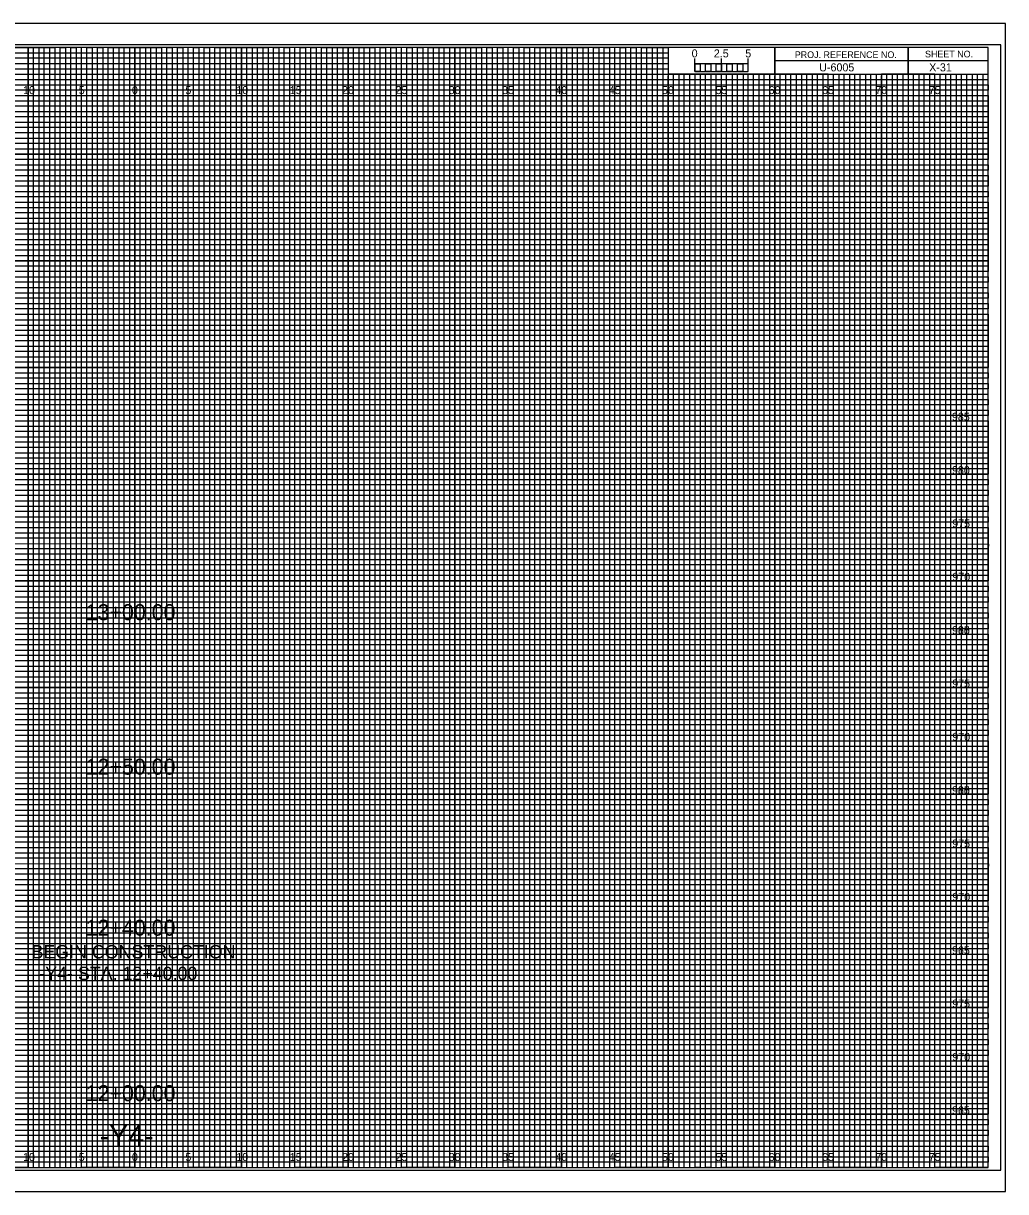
# Model space of a CAD drawing. Extents: x -7 to 162, y -2 to 107.
# Drawn here: x 69.5 to 161.7, y -2.3 to 107.3 of the extents above; entities that cross this region are included whole.
import ezdxf

# ---------------------------------------------------------------- set-up
doc = ezdxf.new("R2010")
doc.units = 0
for name, color, linetype in [('Prop XS Alignment Label', 7, 'Continuous'), ('Prop XS Bar Scale Labels', 7, 'Continuous'), ('Prop XS Elevation Labels', 7, 'Continuous'), ('Prop XS Label Text', 7, 'Continuous'), ('Prop XS Offset Labels', 7, 'Continuous'), ('Prop XS Project Number', 7, 'Continuous'), ('Prop XS Sheet Number', 7, 'Continuous'), ('Prop XS Station Labels', 7, 'Continuous'), ('Sheet Cross Section CELL', 7, 'Continuous'), ('Sheet Cross Section Grid Major CELL', 7, 'Continuous'), ('Sheet Cross Section Grid Middle CELL', 7, 'Continuous'), ('Sheet Cross Section Grid Minor 1 CELL', 7, 'Continuous'), ('Sheet Cross Section Grid Minor 2 CELL', 7, 'Continuous'), ('Sheet Cross Section Scale CELL', 7, 'Continuous'), ('Sheet Cutting Line CELL', 7, 'Continuous'), ('Sheet DOT Grid CELL', 7, 'Continuous'), ('Sheet Plot Border Inside CELL', 7, 'Continuous'), ('Sheet Plot Border Outside CELL', 7, 'Continuous')]:
    doc.layers.add(name, color=color, linetype=linetype)

msp = doc.modelspace()

# ---------------------------------------------------------------- linework, layer by layer
at = {"layer": 'Sheet Cross Section CELL'}
for p, q in [((152.5, 105), (152.5, 102.5)), ((152.5, 102.5), (152.5, 105)), ((160, 103.75), (140, 103.75)), ((140, 103.75), (140, 102.5)), ((140, 102.5), (160, 102.5))]:
    msp.add_line(p, q, dxfattribs=at)
for points in [[(160, 105), (0, 105), (0, 0), (160, 0)], [(140, 105), (130, 105), (130, 102.52), (140, 102.52)], [(160, 105), (140, 105), (140, 102.5), (160, 102.5)]]:
    msp.add_lwpolyline(points, close=True, dxfattribs=at)
at = {"layer": 'Sheet Cross Section Grid Major CELL'}
for p, q in [((75, 105), (70, 105)), ((70, 105), (70, 0)), ((75, 0), (75, 105)), ((85, 105), (80, 105)), ((80, 105), (80, 0)), ((85, 0), (85, 105)), ((95, 105), (90, 105)), ((90, 105), (90, 0)), ((95, 0), (95, 105)), ((105, 105), (100, 105)), ((100, 105), (100, 0)), ((105, 0), (105, 105)), ((115, 105), (110, 105)), ((110, 105), (110, 0)), ((115, 0), (115, 105)), ((125, 105), (120, 105)), ((120, 105), (120, 0)), ((125, 0), (125, 105)), ((130, 105), (130, 0)), ((135, 0), (135, 102.5)), ((145, 102.5), (140, 102.5)), ((140, 102.5), (140, 0)), ((145, 0), (145, 102.5)), ((155, 102.5), (150, 102.5)), ((150, 102.5), (150, 0)), ((155, 0), (155, 102.5)), ((70, 0), (65, 0)), ((80, 0), (75, 0)), ((90, 0), (85, 0)), ((100, 0), (95, 0)), ((110, 0), (105, 0)), ((120, 0), (115, 0)), ((130, 0), (125, 0)), ((140, 0), (135, 0)), ((150, 0), (145, 0)), ((160, 0), (155, 0)), ((160, 0), (160, 0))]:
    msp.add_line(p, q, dxfattribs=at)
for points in [[(0, 100), (160, 100), (160, 95), (0, 95)], [(0, 90), (160, 90), (160, 85), (0, 85)], [(0, 80), (160, 80), (160, 75), (0, 75)], [(0, 70), (160, 70), (160, 65), (0, 65)], [(0, 60), (160, 60), (160, 55), (0, 55)], [(0, 50), (160, 50), (160, 45), (0, 45)], [(0, 40), (160, 40), (160, 35), (0, 35)], [(0, 30), (160, 30), (160, 25), (0, 25)], [(0, 20), (160, 20), (160, 15), (0, 15)], [(0, 10), (160, 10), (160, 5), (0, 5)]]:
    msp.add_lwpolyline(points, dxfattribs=at)
at = {"layer": 'Sheet Cross Section Grid Middle CELL'}
for points in [[(67.5, 105), (72.5, 105), (72.5, 0), (77.5, 0), (77.5, 105), (82.5, 105), (82.5, 0), (87.5, 0), (87.5, 105), (92.5, 105), (92.5, 0), (97.5, 0), (97.5, 105), (102.5, 105), (102.5, 0), (107.5, 0), (107.5, 105), (112.5, 105), (112.5, 0), (117.5, 0), (117.5, 105), (122.5, 105), (122.5, 0), (127.5, 0), (127.5, 105), (129.97, 105), (130, 105), (130, 102.5), (132.5, 102.5), (132.5, 0), (137.5, 0), (137.5, 102.5), (142.5, 102.5), (142.5, 0), (147.5, 0), (147.5, 102.5), (152.5, 102.5), (152.5, 0), (157.5, 0), (157.5, 102.5)], [(0, 102.5), (137.5, 102.5)], [(0, 92.5), (160, 92.5), (160, 97.5), (0, 97.5)], [(0, 82.5), (160, 82.5), (160, 87.5), (0, 87.5)], [(0, 72.5), (160, 72.5), (160, 77.5), (0, 77.5)], [(0, 62.5), (160, 62.5), (160, 67.5), (0, 67.5)], [(0, 52.5), (160, 52.5), (160, 57.5), (0, 57.5)], [(0, 42.5), (160, 42.5), (160, 47.5), (0, 47.5)], [(0, 32.5), (160, 32.5), (160, 37.5), (0, 37.5)], [(0, 22.5), (160, 22.5), (160, 27.5), (0, 27.5)], [(0, 12.5), (160, 12.5), (160, 17.5), (0, 17.5)], [(0, 2.5), (160, 2.5), (160, 7.5), (0, 7.5)]]:
    msp.add_lwpolyline(points, dxfattribs=at)
at = {"layer": 'Sheet Cross Section Grid Minor 1 CELL'}
for p, q in [((0, 104.5), (130, 104.5)), ((130, 104.5), (130, 103.99)), ((130, 103.99), (0, 103.99)), ((0, 103.5), (130, 103.5)), ((130, 102.95), (0, 102.95)), ((130, 103.5), (130, 102.95)), ((0, 102), (160, 102))]:
    msp.add_line(p, q, dxfattribs=at)
for points in [[(0, 101.5), (135, 101.5), (160, 101.5), (160, 101), (0, 101)], [(0, 100.5), (160, 100.5), (160, 99.5), (0, 99.5)], [(0, 99), (160, 99), (160, 98.5), (0, 98.49)], [(0, 98), (160, 98), (160, 97), (0, 97)], [(0, 96.5), (160, 96.5), (160, 96), (0, 96)], [(0, 95.5), (160, 95.5), (160, 94.5), (0, 94.5)], [(0, 94), (160, 94), (160, 93.5), (0, 93.5)], [(0, 93), (160, 93), (160, 92), (0, 92)], [(0, 91.5), (160, 91.5), (160, 91), (0, 91)], [(0, 90.5), (160, 90.5), (160, 89.5), (0, 89.5)], [(0, 89), (160, 89), (160, 88.5), (0, 88.5)], [(0, 88), (160, 88), (160, 86.98), (160, 86.5), (160, 86), (0, 86)], [(0, 87), (160, 87), (160, 86.5), (0, 86.5)], [(0, 85.5), (160, 85.5), (160, 84.5), (0, 84.52)], [(0, 84.52), (160, 84.5), (160, 84), (0, 84)], [(0, 83.5), (160, 83.5), (160, 83), (0, 83)], [(0, 82), (160, 82), (160, 81.5), (0, 81.5)], [(0, 81), (160, 81), (160, 80.5), (0, 80.5)], [(-0.04, 79.45), (160, 79.45), (160, 78.94), (-0.04, 78.94)], [(0, 78.5), (160, 78.5), (160, 78), (0, 78)], [(0, 77), (160, 77), (160, 76.5), (0, 76.5)], [(0, 76), (160, 76), (160, 75.5), (0, 75.5)], [(0, 74.5), (160, 74.5), (160, 74), (0, 74)], [(0, 73.5), (160, 73.5), (160, 73), (0, 73)], [(0, 72), (160, 72), (160, 71.5), (0, 71.5)], [(0, 71), (160, 71), (160, 70.5), (0, 70.5)], [(0, 69.5), (160, 69.5), (160, 68.99), (0, 69)], [(0, 68.5), (160, 68.5), (160, 68), (0, 68)], [(0, 67), (160, 67), (160, 66.5), (0, 66.5)], [(0, 66), (160, 66), (160, 65.5), (0, 65.5)], [(0, 64.5), (160, 64.5), (160, 64), (0, 64)], [(0, 63.5), (160, 63.5), (160, 63), (0, 63)], [(0, 62), (160, 62), (160, 61.5), (0, 61.5)], [(0, 61), (160, 61), (160, 60.5), (0, 60.5)], [(0, 59.5), (160, 59.5), (160, 59), (0, 59)], [(0, 58.5), (160.03, 58.45), (160, 58), (0, 58)], [(0, 57), (160, 57), (160, 56.5), (0, 56.5)], [(0, 56), (160, 56), (160, 55.5), (0, 55.5)], [(0, 54.5), (160, 54.5), (160, 54), (0, 54)], [(0, 53.5), (160, 53.5), (160, 53), (0, 53)], [(0, 52), (160, 52), (160, 51.5), (0, 51.5)], [(0, 51), (160, 51), (160, 50.5), (0, 50.5)], [(0, 49.5), (160, 49.5), (160, 49), (0, 49)], [(0, 48.5), (160, 48.5), (160, 48), (0, 48)], [(0, 47), (160, 47), (160, 46.5), (0, 46.5)], [(0, 46), (160, 46), (160, 45.5), (0, 45.5)], [(0, 44.5), (160, 44.5), (160, 44), (0, 44)], [(0, 43.5), (160, 43.5), (160, 43), (0, 43)], [(0, 42), (160, 42), (160, 41.5), (0, 41.5)], [(0, 41), (160, 41), (160, 40.5), (0, 40.5)], [(0, 39.5), (160, 39.5), (160, 38.99), (0, 39)], [(0, 38.5), (160, 38.5), (160, 38), (0, 38)], [(0, 37), (160, 37), (160, 36.5), (0, 36.5)], [(0, 36), (160, 36), (160, 35.5), (0, 35.5)], [(0, 34.5), (160, 34.5), (160, 34), (0, 34)], [(0, 33.5), (160, 33.5), (160, 33), (0, 33)], [(0, 32), (160, 32), (160, 31.5), (0, 31.5)], [(0, 31), (160, 31), (160, 30.5), (0, 30.5)], [(0, 29.5), (160, 29.5), (160, 29), (0, 29)], [(0, 28.5), (160.03, 28.46), (160, 28), (0, 28)], [(0, 27), (160, 27), (160, 26.5), (0, 26.5)], [(0, 26), (160, 26), (160, 25.5), (0, 25.5)], [(0, 24.5), (160, 24.5), (160, 24), (0, 24)], [(0, 23.5), (160, 23.5), (160, 23), (0, 23)], [(0, 22), (160, 22), (160, 21.5), (0, 21.5)], [(0, 21), (160, 21), (160, 20.5), (0, 20.5)], [(0, 19.5), (160, 19.5), (160, 19), (0, 19)], [(0, 18.5), (160, 18.5), (160, 18), (0, 18)], [(0, 17), (160, 17), (160, 16.5), (0, 16.5)], [(0, 16), (160, 16), (160, 15.5), (0, 15.5)], [(0, 14.5), (160, 14.5), (160, 14), (0, 14)], [(0, 13.5), (160, 13.5), (160, 13), (0, 13)], [(0, 12), (160, 12), (160, 11.5), (0, 11.5)], [(0, 11), (160, 11), (160, 10.5), (0, 10.5)], [(0, 9.5), (160, 9.5), (160, 9), (0, 9)], [(0, 8.5), (160, 8.5), (160, 8), (0, 8)], [(0, 7), (160, 7), (160, 6.5), (0, 6.5)], [(0, 6), (160, 6), (160, 5.5), (0, 5.5)], [(0, 4.5), (160, 4.5), (160, 4), (0, 4)], [(0, 3.5), (160, 3.5), (160, 3), (0, 3)], [(0, 2), (160, 2), (160, 1.5), (0, 1.5)], [(0, 1), (160, 1), (160, 0.5), (0, 0.5)]]:
    msp.add_lwpolyline(points, dxfattribs=at)
at = {"layer": 'Sheet Cross Section Grid Minor 2 CELL'}
for p, q in [((133.5, 102.5), (133, 102.5)), ((133, 102.5), (133, 0)), ((133.5, 0), (133.5, 102.5)), ((134.5, 102.5), (134, 102.5)), ((134, 102.5), (134, 0)), ((134.5, 0), (134.5, 102.5)), ((133, 0), (132.5, 0)), ((134, 0), (133.5, 0))]:
    msp.add_line(p, q, dxfattribs=at)
for points in [[(70, 0), (70.5, 0), (70.5, 105), (71, 105), (71, 0)], [(71, 0), (71.5, 0), (71.5, 105), (72, 105), (72, 0)], [(72.5, 0), (73, 0), (73, 105), (73.5, 105), (73.5, 0)], [(73.5, 0), (74, 0), (74, 105), (74.5, 105), (74.5, 0)], [(75, 0), (75.5, 0), (75.5, 105), (76, 105), (76, 0)], [(76, 0), (76.5, 0), (76.5, 105), (77, 105), (77, 0)], [(77.5, 0), (78, 0), (78, 105), (78.5, 105), (78.5, 0)], [(78.5, 0), (79, 0), (79, 105), (79.5, 105), (79.5, 0)], [(80, 0), (80.5, 0), (80.5, 105), (81, 105), (81, 0)], [(81, 0), (81.5, 0), (81.5, 105), (82, 105), (82, 0)], [(82.5, 0), (83, 0), (83, 105), (83.5, 105), (83.5, 0)], [(83.5, 0), (84, 0), (84, 105), (84.5, 105), (84.5, 0)], [(85, 0), (85.5, 0), (85.5, 105), (86, 105), (86, 0)], [(86, 0), (86.5, 0), (86.5, 105), (87, 105), (87, 0)], [(87.5, 0), (88, 0), (88, 105), (88.5, 105), (88.5, 0)], [(88.5, 0), (89, 0), (89, 105), (89.5, 105), (89.5, 0)], [(90, 0), (90.5, 0), (90.5, 105), (91, 105), (91, 0)], [(91, 0), (91.5, 0), (91.5, 105), (92, 105), (92, 0)], [(92.5, 0), (93, 0), (93, 105), (93.5, 105), (93.5, 0)], [(93.5, 0), (94, 0), (94, 105), (94.5, 105), (94.5, 0)], [(95, 0), (95.5, 0), (95.5, 105), (96, 105), (96, 0)], [(96, 0), (96.5, 0), (96.5, 105), (97, 105), (97, 0)], [(97.5, 0), (98, 0), (98, 105), (98.5, 105), (98.5, 0)], [(98.5, 0), (99, 0), (99, 105), (99.5, 105), (99.5, 0)], [(100, 0), (100.5, 0), (100.5, 105), (101, 105), (101, 0)], [(101, 0), (101.5, 0), (101.5, 105), (102, 105), (102, 0)], [(102.5, 0), (103, 0), (103, 105), (103.5, 105), (103.5, 0)], [(103.5, 0), (104, 0), (104, 105), (104.5, 105), (104.5, 0)], [(105, 0), (105.5, 0), (105.5, 105), (106, 105), (106, 0)], [(106, 0), (106.5, 0), (106.5, 105), (107, 105), (107, 0)], [(107.5, 0), (108, 0), (108, 105), (108.5, 105), (108.5, 0)], [(108.5, 0), (109, 0), (109, 105), (109.5, 105), (109.5, 0)], [(110, 0), (110.5, 0), (110.5, 105), (111, 105), (111, 0)], [(111, 0), (111.5, 0), (111.5, 105), (112, 105), (112, 0)], [(112.5, 0), (113, 0), (113, 105), (113.5, 105), (113.5, 0)], [(113.5, 0), (114, 0), (114, 105), (114.5, 105), (114.5, 0)], [(115, 0), (115.5, 0), (115.5, 105), (116, 105), (116, 0)], [(116, 0), (116.5, 0), (116.5, 105), (117, 105), (117, 0)], [(117.5, 0), (118, 0), (118, 105), (118.5, 105), (118.5, 0)], [(118.5, 0), (119, 0), (119, 105), (119.5, 105), (119.5, 0)], [(120, 0), (120.5, 0), (120.5, 105), (121, 105), (121, 0)], [(121, 0), (121.5, 0), (121.5, 105), (122, 105), (122, 0)], [(122.5, 0), (123, 0), (123, 105), (123.5, 105), (123.5, 0)], [(123.5, 0), (124, 0), (124, 105), (124.5, 105), (124.5, 0)], [(125, 0), (125.5, 0), (125.5, 105), (126, 105), (126, 0)], [(126, 0), (126.5, 0), (126.5, 105), (127, 105), (127, 0)], [(127.5, 0), (128, 0), (128, 105), (128.5, 105), (128.5, 0)], [(128.5, 0), (129, 0), (129, 105), (129.5, 105), (129.5, 0)], [(130, 0), (130.5, 0), (130.5, 102.5), (131.01, 102.5), (131.01, 0)], [(131, 0), (131.5, 0), (131.5, 102.5), (132, 102.5), (132, 0)], [(135, 0), (135.49, 0), (135.49, 102.5), (136, 102.5), (136, 0)], [(136, 0), (136.5, 0), (136.5, 102.5), (137.03, 102.5), (137.03, 0)], [(137.5, 0), (138, 0), (138, 102.5), (138.5, 102.5), (138.5, 0)], [(138.5, 0), (139, 0), (139, 102.5), (139.5, 102.5), (139.5, 0)], [(140, 0), (140.5, 0), (140.5, 102.5), (141, 102.5), (141, 0)], [(141, 0), (141.5, 0), (141.5, 102.5), (142, 102.5), (142, 0)], [(142.5, 0), (143, 0), (143, 102.5), (143.5, 102.5), (143.5, 0)], [(143.5, 0), (144, 0), (144, 102.5), (144.5, 102.5), (144.5, 0)], [(145, 0), (145.5, 0), (145.5, 102.5), (146, 102.5), (146, 0)], [(146, 0), (146.5, 0), (146.5, 102.5), (147, 102.5), (147, 0)], [(147.5, 0), (148, 0), (148, 102.5), (148.5, 102.5), (148.5, 0)], [(148.5, 0), (149, 0), (149, 102.5), (149.5, 102.5), (149.5, 0)], [(150, 0), (150.5, 0), (150.5, 102.5), (151, 102.5), (151, 0)], [(151, 0), (151.5, 0), (151.5, 102.5), (152, 102.5), (152, 0)], [(152.5, 0), (153, 0), (153, 102.5), (153.5, 102.5), (153.5, 0)], [(153.5, 0), (154, 0), (154, 102.5), (154.5, 102.5), (154.5, 0)], [(155, 0), (155.5, 0), (155.5, 102.5), (156, 102.5), (156, 0)], [(156, 0), (156.5, 0), (156.5, 102.5), (157, 102.5), (157, 0)], [(157.5, 0), (158, 0), (158, 102.5), (158.5, 102.5), (158.5, 0)], [(158.5, 0), (159, 0), (159, 102.5), (159.5, 102.5), (159.5, 0)]]:
    msp.add_lwpolyline(points, dxfattribs=at)
at = {"layer": 'Sheet Cross Section Scale CELL'}
for p, q in [((132.5, 102.75), (132.5, 103.95)), ((132.5, 103.45), (132.5, 103.95)), ((135, 102.75), (135, 103.95)), ((137.5, 102.75), (137.5, 103.95)), ((137.5, 103.45), (137.5, 103.95))]:
    msp.add_line(p, q, dxfattribs=at)
for points in [[(137.5, 103.45), (132.5, 103.45), (132.5, 102.75), (137.5, 102.75)], [(132.5, 103.45), (133, 103.45), (133, 102.75), (132.5, 102.75)], [(133.5, 103.45), (134, 103.45), (134, 102.75), (133.5, 102.75)], [(134.5, 103.45), (135, 103.45), (135, 102.75), (134.5, 102.75)], [(135.5, 103.45), (136, 103.45), (136, 102.75), (135.5, 102.75)], [(136.5, 103.45), (137, 103.45), (137, 102.75), (136.5, 102.75)]]:
    msp.add_lwpolyline(points, close=True, dxfattribs=at)
at = {"layer": 'Sheet Cutting Line CELL'}
for p, q in [((161.65, 107.25), (-6.7, 107.25)), ((-6.7, -2.25), (161.65, -2.25))]:
    msp.add_line(p, q, dxfattribs=at)
at = {"layer": 'Sheet DOT Grid CELL'}
for p, q in [((70, 0), (70, 105)), ((75, 0), (75, 105)), ((80, 0), (80, 105)), ((85, 0), (85, 105)), ((90, 0), (90, 105)), ((95, 0), (95, 105)), ((100, 0), (100, 105)), ((105, 0), (105, 105)), ((110, 0), (110, 105)), ((115, 0), (115, 105)), ((120, 0), (120, 105)), ((125, 0), (125, 105)), ((130, 0), (130, 102.34)), ((135, 0), (135, 102.34)), ((140, 0), (140, 102.34)), ((145, 0), (145, 102.34)), ((150, 0), (150, 102.34)), ((155, 0), (155, 102.34)), ((0, 100), (160, 100)), ((0, 95), (160, 95)), ((0, 90), (160, 90)), ((0, 85), (160, 85)), ((0, 80), (160, 80)), ((0, 75), (160, 75)), ((0, 70), (160, 70)), ((0, 65), (160, 65)), ((0, 60), (160, 60)), ((0, 55), (160, 55)), ((0, 50), (160, 50)), ((0, 45), (160, 45)), ((0, 40), (160, 40)), ((0, 35), (160, 35)), ((0, 30), (160, 30)), ((0, 25), (160, 25)), ((0, 20), (160, 20)), ((0, 15), (160, 15)), ((0, 10), (160, 10)), ((0, 5), (160, 5))]:
    msp.add_line(p, q, dxfattribs=at)
at = {"layer": 'Sheet Plot Border Inside CELL'}
msp.add_lwpolyline([(-5.4, -0.25), (161.2, -0.25), (161.2, 105.25), (-5.4, 105.25)], close=True, dxfattribs=at)
at = {"layer": 'Sheet Plot Border Outside CELL'}
msp.add_lwpolyline([(-6.7, -2.25), (161.65, -2.25), (161.65, 107.25), (-6.7, 107.25)], close=True, dxfattribs=at)

# ---------------------------------------------------------------- texts
at = {"layer": 'Prop XS Alignment Label'}
msp.add_text('-Y4-', height=2, dxfattribs=at).set_placement((76.7, 2))
at = {"layer": 'Prop XS Bar Scale Labels'}
for s, p in [('2.5', (134.29, 104.06)), ('5', (137.24, 104.06))]:
    msp.add_text(s, height=0.75, dxfattribs=at).set_placement(p)
at = {"layer": 'Prop XS Elevation Labels'}
for s, p in [('985', (156.61, 70)), ('980', (156.62, 65)), ('975', (156.64, 60)), ('970', (156.65, 55)), ('980', (156.62, 50)), ('965', (156.62, 50)), ('975', (156.64, 45)), ('970', (156.65, 40)), ('980', (156.62, 35)), ('965', (156.62, 35)), ('975', (156.64, 30)), ('970', (156.65, 25)), ('965', (156.62, 20)), ('975', (156.64, 15)), ('970', (156.65, 10)), ('965', (156.62, 5))]:
    msp.add_text(s, height=0.75, dxfattribs=at).set_placement(p)
at = {"layer": 'Prop XS Label Text'}
for s, p in [('BEGIN CONSTRUCTION', (70.31, 19.61)), ('-Y4- STA. 12+40.00', (71.04, 17.58))]:
    msp.add_text(s, height=1.25, dxfattribs=at).set_placement(p)
at = {"layer": 'Prop XS Offset Labels'}
for s, p in [('10', (69.52, 100.62)), ('5', (74.74, 100.62)), ('0', (79.73, 100.62)), ('0', (79.73, 100.62)), ('5', (84.74, 100.62)), ('10', (89.52, 100.62)), ('15', (94.53, 100.62)), ('20', (99.43, 100.62)), ('25', (104.44, 100.62)), ('30', (109.43, 100.62)), ('35', (114.44, 100.62)), ('40', (119.43, 100.62)), ('45', (124.44, 100.62)), ('50', (129.43, 100.62)), ('55', (134.44, 100.62)), ('60', (139.43, 100.62)), ('65', (144.44, 100.62)), ('70', (149.43, 100.62)), ('75', (154.44, 100.62)), ('10', (69.52, 0.62)), ('5', (74.74, 0.62)), ('0', (79.73, 0.62)), ('0', (79.73, 0.62)), ('5', (84.74, 0.62)), ('10', (89.52, 0.62)), ('15', (94.53, 0.62)), ('20', (99.43, 0.62)), ('25', (104.44, 0.62)), ('30', (109.43, 0.62)), ('35', (114.44, 0.62)), ('40', (119.43, 0.62)), ('45', (124.44, 0.62)), ('50', (129.43, 0.62)), ('55', (134.44, 0.62)), ('60', (139.43, 0.62)), ('65', (144.44, 0.62)), ('70', (149.43, 0.62)), ('75', (154.44, 0.62))]:
    msp.add_text(s, height=0.75, dxfattribs=at).set_placement(p)
at = {"layer": 'Prop XS Project Number'}
msp.add_text('U-6005', height=0.75, dxfattribs=at).set_placement((144.17, 102.75))
at = {"layer": 'Prop XS Sheet Number'}
msp.add_text('X-31', height=0.75, dxfattribs=at).set_placement((154.48, 102.75))
at = {"layer": 'Prop XS Station Labels'}
for s, p in [('13+00.00', (75.39, 51.31)), ('12+50.00', (75.39, 36.83)), ('12+40.00', (75.39, 21.74)), ('12+00.00', (75.39, 6.23))]:
    msp.add_text(s, height=1.5, dxfattribs=at).set_placement(p)
at = {"layer": 'Sheet Cross Section CELL'}
for s, p in [('PROJ. REFERENCE NO.', (141.88, 104)), ('SHEET NO.', (154.09, 104.06))]:
    msp.add_text(s, height=0.625, dxfattribs=at).set_placement(p)
at = {"layer": 'Sheet Cross Section Scale CELL'}
msp.add_text('0', height=0.75, dxfattribs=at).set_placement((132.21, 104.06))

doc.saveas('drawing.dxf')
